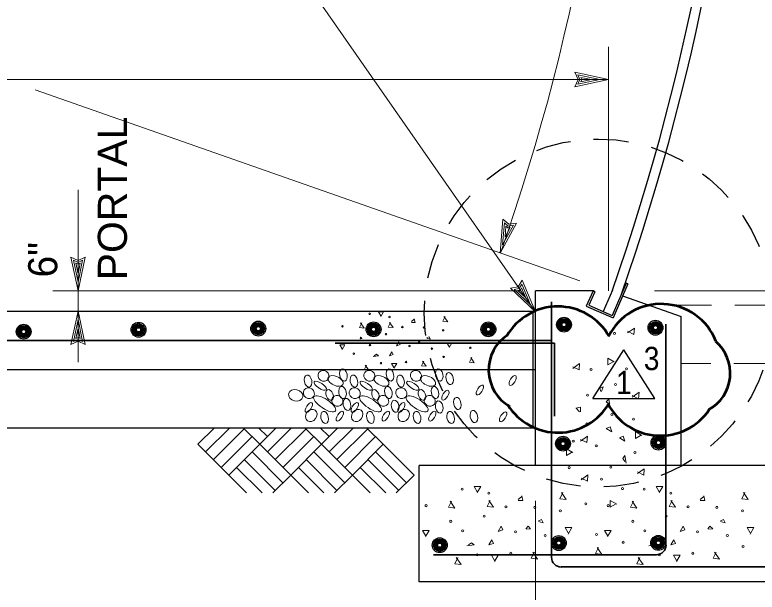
# Model space of a CAD drawing. Extents: x -24.3 to 17.7, y -17.6 to 12.4.
# Drawn here: x -5.978 to -2.791, y -12.561 to -10.082 of the extents above; entities that cross this region are included whole.
import ezdxf
from ezdxf.enums import TextEntityAlignment as Align

# ---------------------------------------------------------------- set-up
doc = ezdxf.new("R2010")
doc.units = 0
doc.header["$LTSCALE"] = 0.05
doc.linetypes.add('MEDIUM_DASHED', pattern=[4.5, 3, -1.5])
doc.layers.add('1', color=7, linetype='Continuous', lineweight=13)
doc.layers.add('2', color=7, linetype='Continuous', lineweight=13)

msp = doc.modelspace()

# ---------------------------------------------------------------- linework, layer by layer
at = {"layer": '1'}
for p, q in [((-3.42969, -11.2666), (-3.42969, -10.2186)), ((-3.42969, -10.3596), (-3.57369, -10.3286)), ((-3.46669, -10.3596), (-3.56069, -10.3396)), ((-3.55169, -10.3596), (-3.56069, -10.3396)), ((-3.50269, -10.3596), (-3.54769, -10.3506)), ((-3.54369, -10.3596), (-3.54769, -10.3506)), ((-3.46669, -10.3596), (-3.56069, -10.3796)), ((-3.56069, -10.3796), (-3.55169, -10.3596)), ((-3.50269, -10.3596), (-3.54769, -10.3696)), ((-3.54769, -10.3696), (-3.54369, -10.3596)), ((-3.55269, -11.2246), (-5.89069, -10.4036)), ((-3.89369, -11.1056), (-3.88269, -10.9586)), ((-3.89369, -11.1056), (-3.82369, -10.9766)), ((-3.88369, -11.0696), (-3.87569, -10.9746)), ((-3.88369, -11.0696), (-3.83769, -10.9856)), ((-3.87569, -10.9746), (-3.85969, -10.9886)), ((-3.87269, -11.0356), (-3.86969, -10.9896)), ((-3.86969, -10.9896), (-3.86169, -10.9966)), ((-3.85969, -10.9886), (-3.83769, -10.9856)), ((-3.87269, -11.0356), (-3.85169, -10.9946)), ((-3.86169, -10.9966), (-3.85169, -10.9946)), ((-5.70669, -11.2666), (-5.73769, -11.1226)), ((-5.70669, -11.2296), (-5.72669, -11.1356)), ((-5.72669, -11.1356), (-5.70669, -11.1446)), ((-5.70669, -11.1936), (-5.71669, -11.1486)), ((-5.71669, -11.1486), (-5.70669, -11.1526)), ((-5.70669, -11.2666), (-5.67569, -11.1226)), ((-5.70669, -11.2296), (-5.68669, -11.1356)), ((-5.70669, -11.1446), (-5.68669, -11.1356)), ((-5.70669, -11.1936), (-5.69769, -11.1486)), ((-5.70669, -11.1526), (-5.69769, -11.1486)), ((-3.81269, -11.2566), (-3.80069, -11.2376)), ((-3.76369, -11.3266), (-3.80069, -11.2376)), ((-3.74269, -11.3566), (-3.79969, -11.2206)), ((-3.80669, -11.2666), (-5.81469, -11.2666)), ((-3.83369, -11.2606), (-3.81269, -11.2566)), ((-3.76369, -11.3266), (-3.83369, -11.2606)), ((-3.81869, -11.2656), (-3.80769, -11.2626)), ((-3.78469, -11.2966), (-3.81869, -11.2656)), ((-3.80769, -11.2626), (-3.80269, -11.2546)), ((-3.78469, -11.2966), (-3.80269, -11.2546)), ((-3.23169, -11.2666), (-0.82769, -11.2666)), ((-5.70669, -11.3536), (-5.73769, -11.4976)), ((-5.70669, -11.3536), (-5.67569, -11.4976)), ((-5.70669, -11.5726), (-5.70669, -11.3536)), ((-5.70669, -11.3906), (-5.72669, -11.4846)), ((-5.70669, -11.3906), (-5.68669, -11.4846)), ((-5.70669, -11.4266), (-5.71569, -11.4716)), ((-5.70669, -11.4266), (-5.69669, -11.4716)), ((-5.70669, -11.4676), (-5.71569, -11.4716)), ((-5.69669, -11.4716), (-5.70669, -11.4676)), ((-5.70669, -11.4756), (-5.72669, -11.4846)), ((-5.68669, -11.4846), (-5.70669, -11.4756)), ((-5.19169, -11.9256), (-5.12069, -11.8546)), ((-5.15869, -11.9586), (-5.05469, -11.8546)), ((-5.12569, -11.9916), (-4.99269, -11.8596)), ((-4.92669, -11.9256), (-4.99769, -11.8546)), ((-4.89369, -11.8926), (-4.93169, -11.8546)), ((-4.92669, -11.9256), (-4.85569, -11.8546)), ((-4.92669, -11.9256), (-4.85569, -11.8546)), ((-4.89369, -11.9586), (-4.78969, -11.8546)), ((-4.86069, -11.8596), (-4.86569, -11.8546)), ((-4.86069, -11.9916), (-4.72769, -11.8596)), ((-4.66169, -11.9256), (-4.73269, -11.8546)), ((-4.62869, -11.8926), (-4.66669, -11.8546)), ((-4.66169, -11.9256), (-4.59069, -11.8546)), ((-4.62869, -11.9586), (-4.52369, -11.8546)), ((-4.59569, -11.8596), (-4.59969, -11.8546)), ((-4.59569, -11.9916), (-4.46269, -11.8596)), ((-4.39669, -11.9256), (-4.46769, -11.8546)), ((-5.09269, -12.0256), (-4.95969, -11.8926)), ((-4.82769, -12.0256), (-4.69469, -11.8926)), ((-4.56169, -12.0256), (-4.42969, -11.8926)), ((-5.05969, -12.0586), (-4.92669, -11.9256)), ((-4.79369, -12.0586), (-4.92669, -11.9256)), ((-4.79369, -12.0586), (-4.66169, -11.9256)), ((-4.52869, -12.0586), (-4.39669, -11.9256)), ((-4.26369, -12.0586), (-4.39669, -11.9256)), ((-4.82769, -12.0916), (-4.95969, -11.9586)), ((-4.56169, -12.0916), (-4.69469, -11.9586)), ((-4.29669, -12.0916), (-4.42969, -11.9586)), ((-4.86069, -12.1246), (-4.99269, -11.9916)), ((-4.59569, -12.1246), (-4.72769, -11.9916)), ((-4.32969, -12.1246), (-4.46269, -11.9916)), ((-4.91669, -12.1346), (-5.02669, -12.0256)), ((-4.65169, -12.1346), (-4.76069, -12.0256)), ((-4.38569, -12.1346), (-4.49569, -12.0256)), ((-4.87069, -12.1346), (-4.79369, -12.0586)), ((-4.71769, -12.1346), (-4.79369, -12.0586)), ((-4.60569, -12.1346), (-4.52869, -12.0586)), ((-4.34069, -12.1346), (-4.26369, -12.0586)), ((-3.74269, -14.5116), (-3.74269, -12.1686))]:
    msp.add_line(p, q, dxfattribs=at)
at = {"layer": '1', "lineweight": 25}
for p, q in [((-3.35369, -11.2336), (-3.41369, -11.3726)), ((-3.34569, -11.2366), (-3.40969, -11.3826)), ((-3.34569, -11.2366), (-3.35369, -11.2336)), ((-3.74269, -12.0166), (-3.74269, -11.2666)), ((-3.49469, -11.2666), (-3.74269, -11.2666)), ((-3.49569, -11.2666), (-3.52469, -11.3326)), ((-3.48869, -11.2706), (-3.49569, -11.2666)), ((-3.41269, -11.2646), (-3.45169, -11.3556)), ((-3.36869, -11.2886), (-3.11769, -11.3776)), ((-3.52469, -11.3326), (-3.40969, -11.3826)), ((-16.07569, -11.3546), (-3.74269, -11.3546)), ((-3.75269, -11.8546), (-3.75269, -11.3546)), ((-3.11769, -12.0166), (-3.11769, -11.3776)), ((-3.49654, -11.72945), (-3.36354, -11.52045)), ((-3.23054, -11.72945), (-3.36354, -11.52045)), ((-16.07569, -11.6046), (-3.74269, -11.6046)), ((-3.49654, -11.72945), (-3.23054, -11.72945)), ((-16.07569, -11.8546), (-3.74269, -11.8546)), ((-2.61769, -12.0166), (-4.24269, -12.0166))]:
    msp.add_line(p, q, dxfattribs=at)
at = {"layer": '1', "lineweight": 35}
for p, q in [((-3.67369, -12.4116), (-3.67369, -11.3136)), ((-3.18269, -12.3586), (-3.18269, -11.4106)), ((-9.84169, -11.4796), (-3.67137, -11.4796)), ((-3.6617, -11.49113), (-4.60307, -11.49113)), ((-3.6617, -11.80445), (-3.6617, -11.49113)), ((-4.18069, -12.4006), (-3.22369, -12.4006)), ((-3.63269, -12.4526), (-2.69869, -12.4526))]:
    msp.add_line(p, q, dxfattribs=at)
at = {"layer": '1', "linetype": 'MEDIUM_DASHED'}
for p, q in [((-2.23769, -11.3286), (-3.25769, -11.3286)), ((-2.24069, -11.5786), (-3.11769, -11.5786))]:
    msp.add_line(p, q, dxfattribs=at)
at = {"layer": '1'}
for points in [[(-4.84869, -9.9336), (-4.73269, -9.9336), (-3.74269, -11.3566), (-3.85069, -11.2556)], [(-3.57369, -10.3906), (-3.55969, -10.3596), (-3.57369, -10.3286)], [(-16.38769, -10.3596), (-9.90869, -10.3596), (-3.42969, -10.3596), (-3.57369, -10.3906)], [(-5.70669, -11.3536), (-5.70669, -11.2666), (-5.70669, -10.8326)], [(-3.88269, -10.9586), (-3.85669, -10.9806), (-3.82369, -10.9766)], [(-5.73769, -11.1226), (-5.70669, -11.1366), (-5.67569, -11.1226)], [(-3.85069, -11.2556), (-3.81669, -11.2496), (-3.79969, -11.2206)], [(-5.67569, -11.4976), (-5.70669, -11.4836), (-5.73769, -11.4976)], [(-4.45269, -12.1346), (-4.66169, -11.9256), (-4.59069, -11.8546)], [(-4.98269, -12.1346), (-5.05969, -12.0586), (-5.19169, -11.9256)]]:
    msp.add_lwpolyline(points, dxfattribs=at)
at = {"layer": '1', "lineweight": 25}
for points in [[(-3.48869, -11.2706), (-3.51369, -11.3286), (-3.41369, -11.3726)], [(-2.61769, -12.5166), (-4.24269, -12.5166), (-4.24269, -12.0166)]]:
    msp.add_lwpolyline(points, dxfattribs=at)
at = {"layer": '1', "linetype": 'MEDIUM_DASHED', "lineweight": 25}
msp.add_circle((-3.47269, -11.3626), 0.7473, dxfattribs=at)
at = {"layer": '1', "lineweight": 25}
for centre, radius in [((-5.44683, -11.43413), 0.0319), ((-5.44683, -11.43413), 0.02658), ((-4.93285, -11.42913), 0.0319), ((-4.93285, -11.42913), 0.02658), ((-4.93285, -11.42913), 0.02215), ((-4.43786, -11.43213), 0.0319), ((-4.43786, -11.43213), 0.02658), ((-3.94488, -11.43213), 0.0319), ((-3.94488, -11.43213), 0.02658), ((-3.62022, -11.41221), 0.0319), ((-3.62022, -11.41221), 0.02658), ((-3.62022, -11.41221), 0.02215), ((-3.62022, -11.41221), 0.01846), ((-3.62022, -11.41221), 0.01538), ((-3.62022, -11.41221), 0.01282), ((-3.62022, -11.41221), 0.01068), ((-3.62022, -11.41221), 0.0089), ((-3.22765, -11.42538), 0.0319), ((-3.22765, -11.42538), 0.02658), ((-3.22765, -11.42538), 0.02215), ((-3.22765, -11.42538), 0.01846), ((-5.93981, -11.44213), 0.0319), ((-5.93981, -11.44213), 0.02658), ((-5.93981, -11.44213), 0.02215), ((-5.93981, -11.44213), 0.01846), ((-5.93981, -11.44213), 0.01538), ((-5.93981, -11.44213), 0.01282), ((-5.93981, -11.44213), 0.01068), ((-5.93981, -11.44213), 0.0089), ((-5.44683, -11.43413), 0.02215), ((-5.44683, -11.43413), 0.01846), ((-5.44683, -11.43413), 0.01538), ((-5.44683, -11.43413), 0.01282), ((-5.44683, -11.43413), 0.01068), ((-5.44683, -11.43413), 0.0089), ((-4.93285, -11.42913), 0.01846), ((-4.93285, -11.42913), 0.01538), ((-4.93285, -11.42913), 0.01282), ((-4.93285, -11.42913), 0.01068), ((-4.93285, -11.42913), 0.0089), ((-4.43786, -11.43213), 0.02215), ((-4.43786, -11.43213), 0.01846), ((-4.43786, -11.43213), 0.01538), ((-4.43786, -11.43213), 0.01282), ((-4.43786, -11.43213), 0.01068), ((-4.43786, -11.43213), 0.0089), ((-3.94488, -11.43213), 0.02215), ((-3.94488, -11.43213), 0.01846), ((-3.94488, -11.43213), 0.01538), ((-3.94488, -11.43213), 0.01282), ((-3.94488, -11.43213), 0.01068), ((-3.94488, -11.43213), 0.0089), ((-3.22765, -11.42538), 0.01538), ((-3.22765, -11.42538), 0.01282), ((-3.22765, -11.42538), 0.01068), ((-3.22765, -11.42538), 0.0089), ((-3.62455, -11.92344), 0.0319), ((-3.62455, -11.92344), 0.02658), ((-3.62455, -11.92344), 0.02215), ((-3.62455, -11.92344), 0.01846), ((-3.62455, -11.92344), 0.01538), ((-3.62455, -11.92344), 0.01282), ((-3.62455, -11.92344), 0.01068), ((-3.62455, -11.92344), 0.0089), ((-3.2149, -11.91869), 0.0319), ((-3.2149, -11.91869), 0.02658), ((-3.2149, -11.91869), 0.02215), ((-3.2149, -11.91869), 0.01846), ((-3.2149, -11.91869), 0.01538), ((-3.2149, -11.91869), 0.01282), ((-3.2149, -11.91869), 0.01068), ((-3.2149, -11.91869), 0.0089), ((-4.15379, -12.35935), 0.0319), ((-3.6428, -12.3501), 0.0319), ((-3.6428, -12.3501), 0.02658), ((-3.6428, -12.3501), 0.02215), ((-3.6428, -12.3501), 0.01846), ((-3.21565, -12.34918), 0.0319), ((-3.21565, -12.34918), 0.02658), ((-3.21565, -12.34918), 0.02215), ((-3.21565, -12.34918), 0.01846), ((-4.15379, -12.35935), 0.02658), ((-4.15379, -12.35935), 0.02215), ((-4.15379, -12.35935), 0.01846), ((-4.15379, -12.35935), 0.01538), ((-4.15379, -12.35935), 0.01282), ((-4.15379, -12.35935), 0.01068), ((-4.15379, -12.35935), 0.0089), ((-3.6428, -12.3501), 0.01538), ((-3.6428, -12.3501), 0.01282), ((-3.6428, -12.3501), 0.01068), ((-3.6428, -12.3501), 0.0089), ((-3.21565, -12.34918), 0.01538), ((-3.21565, -12.34918), 0.01282), ((-3.21565, -12.34918), 0.01068), ((-3.21565, -12.34918), 0.0089)]:
    msp.add_circle(centre, radius, dxfattribs=at)
at = {"layer": '1'}
msp.add_arc((-12.59669, -8.0506), 9.224, 340.65884, 359.95031, dxfattribs=at)
at = {"layer": '1', "lineweight": 25}
for radius in [9.70818, 9.74984]:
    msp.add_arc((-12.57569, -8.05836), radius, 340.66927, 359.12919, dxfattribs=at)
at = {"layer": '1', "lineweight": 53}
for centre, radius, start, end in [((-3.64649, -11.58747), 0.25334, 29.90527, 149.99619), ((-3.20334, -11.57661), 0.25334, 21.83431, 152.92582), ((-3.76385, -11.60702), 0.18009, 122.74739, 240.5783), ((-3.08692, -11.62029), 0.18009, 299.4217, 48.99754), ((-3.64649, -11.62265), 0.25334, 211.92276, 330.09473), ((-3.20696, -11.63532), 0.25334, 207.07418, 326.09842)]:
    msp.add_arc(centre, radius, start, end, dxfattribs=at)
at = {"layer": '1', "lineweight": 35}
for centre, start, end in [((-3.22396, -12.35863), 270, 0), ((-3.63237, -12.41133), 180, 270)]:
    msp.add_arc(centre, 0.04167, start, end, dxfattribs=at)
at = {"layer": '1'}
for centre, major_axis, ratio in [((-4.71919, -11.6546), (-0.0055, 0.026), 0.599528), ((-4.65269, -11.6321), (-0.02021, 0.0142), 0.915279), ((-4.60119, -11.6536), (-0.0315, 0.015), 0.562188), ((-4.56719, -11.6286), (-0.0055, 0.026), 0.599528), ((-4.52219, -11.6546), (-0.0055, 0.026), 0.599528), ((-4.45569, -11.6321), (-0.02021, 0.0142), 0.915279), ((-4.40419, -11.6536), (-0.0315, 0.015), 0.562188), ((-4.36719, -11.6286), (-0.0055, 0.026), 0.599528), ((-4.32219, -11.6546), (-0.0055, 0.026), 0.599528), ((-4.25569, -11.6321), (-0.02021, 0.0142), 0.915279), ((-4.20419, -11.6536), (-0.0315, 0.015), 0.562188), ((-4.15619, -11.6286), (-0.0055, 0.026), 0.599528), ((-4.11119, -11.6436), (-0.0055, 0.026), 0.599528), ((-3.84069, -11.6521), (0.013, 0.0205), 0.445558), ((-4.66669, -11.6746), (-0.026, 0.017), 0.365968), ((-4.46969, -11.6746), (-0.026, 0.017), 0.365968), ((-4.26969, -11.6746), (-0.026, 0.017), 0.365968), ((-4.77219, -11.7156), (-0.03038, 0.00696), 0.790099), ((-4.71569, -11.7061), (-0.02021, 0.0142), 0.915279), ((-4.62669, -11.7141), (-0.009, 0.0225), 0.615421), ((-4.57119, -11.7036), (-0.0055, 0.026), 0.599528), ((-4.51869, -11.7061), (-0.02021, 0.0142), 0.915279), ((-4.42969, -11.7141), (-0.009, 0.0225), 0.615421), ((-4.37419, -11.7036), (-0.0055, 0.026), 0.599528), ((-4.31869, -11.7061), (-0.02021, 0.0142), 0.915279), ((-4.22969, -11.7141), (-0.009, 0.0225), 0.615421), ((-4.17419, -11.7036), (-0.0055, 0.026), 0.599528), ((-4.12969, -11.7151), (0.013, 0.0205), 0.445558), ((-3.98169, -11.6931), (0.013, 0.0205), 0.445558), ((-4.64769, -11.7521), (-0.04615, 0.03077), 0.357541), ((-4.59369, -11.7391), (-0.02021, 0.0142), 0.915279), ((-4.45069, -11.7521), (-0.04615, 0.03077), 0.357541), ((-4.39669, -11.7391), (-0.02021, 0.0142), 0.915279), ((-4.25069, -11.7521), (-0.04615, 0.03077), 0.357541), ((-4.19669, -11.7391), (-0.02021, 0.0142), 0.915279), ((-4.07819, -11.7506), (-0.0055, 0.026), 0.599528), ((-4.71569, -11.7681), (0.013, 0.0205), 0.445558), ((-4.55219, -11.7546), (-0.0055, 0.026), 0.599528), ((-4.51869, -11.7681), (0.013, 0.0205), 0.445558), ((-4.34519, -11.7626), (-0.0055, 0.026), 0.599528), ((-4.31869, -11.7681), (0.013, 0.0205), 0.445558), ((-4.15619, -11.7656), (-0.0055, 0.026), 0.599528), ((-4.70519, -11.8021), (0.0165, 0.0225), 0.822116), ((-4.64819, -11.8106), (-0.0055, 0.026), 0.599528), ((-4.58269, -11.8051), (0.013, 0.0205), 0.445558), ((-4.50819, -11.8021), (0.0165, 0.0225), 0.822116), ((-4.45119, -11.8106), (-0.0055, 0.026), 0.599528), ((-4.38569, -11.8051), (0.013, 0.0205), 0.445558), ((-4.30819, -11.8021), (0.0165, 0.0225), 0.822116), ((-4.25119, -11.8106), (-0.0055, 0.026), 0.599528), ((-4.18569, -11.8051), (0.013, 0.0205), 0.445558), ((-4.10719, -11.8106), (-0.0055, 0.026), 0.599528), ((-4.00719, -11.8066), (-0.0055, 0.026), 0.599528), ((-3.88169, -11.8081), (0.013, 0.0205), 0.445558)]:
    msp.add_ellipse(centre, major_axis=major_axis, ratio=ratio, dxfattribs=at)
at = {"layer": '2'}
for p, q in [((-4.27469, -11.3986), (-4.26369, -11.3886)), ((-3.55369, -11.7866), (-3.56769, -11.7706)), ((-3.81769, -12.1626), (-3.80169, -12.1496)), ((-3.03569, -12.1626), (-3.02069, -12.1496))]:
    msp.add_line(p, q, dxfattribs=at)
for points in [[(-4.40669, -11.3736), (-4.41669, -11.3566), (-4.39469, -11.3566), (-4.40669, -11.3776)], [(-4.48869, -11.4046), (-4.49869, -11.4246), (-4.47869, -11.4266), (-4.49369, -11.4046)], [(-4.36469, -11.4026), (-4.37469, -11.4226), (-4.35369, -11.4246), (-4.36969, -11.4026)], [(-4.26369, -11.3876), (-4.25969, -11.4026), (-4.27469, -11.4026)], [(-4.13069, -11.3776), (-4.14069, -11.3976), (-4.11969, -11.3996), (-4.13569, -11.3776)], [(-3.34769, -11.4406), (-3.32069, -11.4546), (-3.31769, -11.4266), (-3.34769, -11.4476)], [(-4.20969, -11.4676), (-4.19969, -11.4646), (-4.19469, -11.4746), (-4.20969, -11.4696)], [(-4.57269, -11.5156), (-4.58269, -11.4986), (-4.56069, -11.4986), (-4.57269, -11.5186)], [(-4.24969, -11.4936), (-4.24269, -11.4846), (-4.23469, -11.4936), (-4.24769, -11.4946)], [(-4.11369, -11.5066), (-4.12369, -11.4896), (-4.10169, -11.4896), (-4.11369, -11.5106)], [(-4.43469, -11.5456), (-4.42469, -11.5386), (-4.41669, -11.5456), (-4.43969, -11.5486)], [(-4.01569, -11.5536), (-4.02569, -11.5736), (-4.00569, -11.5756), (-4.02069, -11.5536)], [(-3.40969, -11.5716), (-3.43269, -11.5846), (-3.43269, -11.5556), (-3.40569, -11.5716)], [(-4.46869, -11.5856), (-4.47869, -11.6056), (-4.45869, -11.6076), (-4.47369, -11.5856)], [(-4.35069, -11.5956), (-4.36069, -11.5786), (-4.33869, -11.5786), (-4.35069, -11.5996)], [(-4.22269, -11.5686), (-4.23269, -11.5886), (-4.21269, -11.5906), (-4.22769, -11.5686)], [(-3.58269, -11.5936), (-3.55569, -11.6066), (-3.55369, -11.5796), (-3.58269, -11.6006)], [(-3.46169, -11.6986), (-3.46669, -11.6856), (-3.45269, -11.6786), (-3.45969, -11.6986)], [(-3.32769, -11.7166), (-3.30069, -11.7306), (-3.29769, -11.7026), (-3.32769, -11.7236)], [(-3.42769, -11.7526), (-3.43969, -11.7436), (-3.42769, -11.7326), (-3.42569, -11.7506)], [(-3.56969, -11.7706), (-3.54969, -11.7666), (-3.54969, -11.7866)], [(-3.29169, -11.8876), (-3.31369, -11.9006), (-3.31369, -11.8716), (-3.28669, -11.8876)], [(-3.54969, -11.9056), (-3.52269, -11.9186), (-3.51969, -11.8916), (-3.54969, -11.9126)], [(-3.58769, -11.9616), (-3.60969, -11.9746), (-3.60969, -11.9456), (-3.58269, -11.9616)], [(-3.35869, -11.9996), (-3.36769, -11.9866), (-3.35869, -11.9746), (-3.35369, -12.0066)], [(-3.30469, -12.0446), (-3.27769, -12.0586), (-3.27569, -12.0306), (-3.30469, -12.0516)], [(-3.54669, -12.0716), (-3.51969, -12.0846), (-3.51769, -12.0576), (-3.54669, -12.0786)], [(-3.99269, -12.1296), (-4.00569, -12.1066), (-3.97669, -12.1066), (-3.99269, -12.1336)], [(-3.21169, -12.1296), (-3.22469, -12.1066), (-3.19569, -12.1066), (-3.21169, -12.1336)], [(-3.62469, -12.1336), (-3.63769, -12.1606), (-3.61069, -12.1636), (-3.63169, -12.1336)], [(-2.84369, -12.1336), (-2.85669, -12.1606), (-2.82969, -12.1636), (-2.84969, -12.1336)], [(-4.10269, -12.1696), (-4.11569, -12.1966), (-4.08869, -12.1996), (-4.10969, -12.1696)], [(-3.93669, -12.1676), (-3.94969, -12.1936), (-3.92269, -12.1966), (-3.94369, -12.1676)], [(-3.80169, -12.1476), (-3.79769, -12.1676), (-3.81769, -12.1676)], [(-3.39869, -12.1836), (-3.42169, -12.1966), (-3.42169, -12.1676), (-3.39369, -12.1836)], [(-3.32169, -12.1696), (-3.33469, -12.1966), (-3.30769, -12.1996), (-3.32769, -12.1696)], [(-3.15569, -12.1676), (-3.16869, -12.1936), (-3.14169, -12.1966), (-3.16169, -12.1676)], [(-3.02069, -12.1476), (-3.01569, -12.1676), (-3.03569, -12.1676)], [(-3.72969, -12.2546), (-3.71669, -12.2496), (-3.70969, -12.2636), (-3.72969, -12.2576)], [(-2.94869, -12.2546), (-2.93569, -12.2496), (-2.92869, -12.2636), (-2.94869, -12.2576)], [(-4.21469, -12.3176), (-4.22769, -12.2956), (-4.19869, -12.2956), (-4.21469, -12.3226)], [(-3.78369, -12.2886), (-3.77469, -12.2776), (-3.76369, -12.2886), (-3.78169, -12.2906)], [(-3.60269, -12.3066), (-3.61569, -12.2836), (-3.58669, -12.2836), (-3.60269, -12.3116)], [(-3.43369, -12.3176), (-3.44669, -12.2956), (-3.41769, -12.2956), (-3.43369, -12.3226)], [(-3.00269, -12.2886), (-2.99369, -12.2776), (-2.98169, -12.2886), (-2.99969, -12.2906)], [(-2.82169, -12.3066), (-2.83469, -12.2836), (-2.80569, -12.2836), (-2.82169, -12.3116)], [(-4.03069, -12.3576), (-4.01769, -12.3496), (-4.00569, -12.3576), (-4.03769, -12.3626)], [(-3.24969, -12.3576), (-3.23569, -12.3496), (-3.22469, -12.3576), (-3.25569, -12.3626)], [(-3.74769, -12.3896), (-3.76169, -12.4156), (-3.73369, -12.4186), (-3.75469, -12.3896)], [(-3.47169, -12.3696), (-3.48569, -12.3956), (-3.45769, -12.3986), (-3.47869, -12.3696)], [(-2.96669, -12.3896), (-2.97969, -12.4156), (-2.95269, -12.4186), (-2.97369, -12.3896)], [(-4.07569, -12.4116), (-4.08969, -12.4386), (-4.06169, -12.4416), (-4.08269, -12.4116)], [(-3.91869, -12.4256), (-3.93169, -12.4026), (-3.90269, -12.4026), (-3.91869, -12.4296)], [(-3.29469, -12.4116), (-3.30769, -12.4386), (-3.28069, -12.4416), (-3.30169, -12.4116)], [(-3.13769, -12.4256), (-3.15069, -12.4026), (-3.12169, -12.4026), (-3.13769, -12.4296)]]:
    msp.add_lwpolyline(points, dxfattribs=at)
for points in [[(-4.33969, -11.5026), (-4.32969, -11.4856), (-4.32369, -11.4976)], [(-4.36969, -11.5456), (-4.35969, -11.5286), (-4.35369, -11.5406)], [(-3.41569, -11.8726), (-3.43869, -11.8586), (-3.42269, -11.8516)], [(-3.35869, -11.9126), (-3.38169, -11.8986), (-3.36569, -11.8916)], [(-3.90369, -12.3006), (-3.88969, -12.2776), (-3.88269, -12.2936)], [(-3.12169, -12.3006), (-3.10869, -12.2776), (-3.10169, -12.2936)], [(-3.94369, -12.3576), (-3.92969, -12.3356), (-3.92269, -12.3516)], [(-3.16169, -12.3576), (-3.14869, -12.3356), (-3.14169, -12.3516)]]:
    msp.add_lwpolyline(points, close=True, dxfattribs=at)
for centre, radius in [((-4.455, -11.36556), 0.00325), ((-4.36951, -11.37906), 0.00325), ((-4.5715, -11.41906), 0.00325), ((-4.31401, -11.42256), 0.00325), ((-4.22151, -11.42456), 0.00325), ((-4.13901, -11.43606), 0.00325), ((-4.492, -11.46956), 0.00325), ((-4.3845, -11.45306), 0.00325), ((-3.40371, -11.44964), 0.00433), ((-4.4535, -11.50006), 0.00325), ((-4.28351, -11.50356), 0.00325), ((-4.5225, -11.53706), 0.00325), ((-4.18751, -11.51506), 0.00325), ((-4.02251, -11.51156), 0.00325), ((-4.13701, -11.55055), 0.00325), ((-4.4065, -11.57755), 0.00325), ((-4.29851, -11.57255), 0.00325), ((-3.35171, -11.6023), 0.00433), ((-3.50437, -11.60497), 0.00433), ((-3.39904, -11.66964), 0.00433), ((-3.51971, -11.71497), 0.00433), ((-3.41437, -11.79763), 0.00433), ((-3.32238, -11.81763), 0.00433), ((-3.52237, -11.8383), 0.00433), ((-3.58037, -11.9123), 0.00433), ((-3.48171, -11.9323), 0.00433), ((-3.31571, -11.96163), 0.00433), ((-3.59837, -12.0263), 0.00433), ((-3.41904, -12.0243), 0.00433), ((-3.45971, -12.07563), 0.00433), ((-4.05741, -12.11813), 0.00433), ((-3.94341, -12.13613), 0.00433), ((-3.36971, -12.1163), 0.00433), ((-3.27588, -12.11813), 0.00433), ((-3.16188, -12.13613), 0.00433), ((-4.21274, -12.18946), 0.00433), ((-3.86941, -12.19413), 0.00433), ((-3.74608, -12.19679), 0.00433), ((-3.52704, -12.18163), 0.00433), ((-3.43121, -12.18946), 0.00433), ((-3.08788, -12.19413), 0.00433), ((-2.96455, -12.19679), 0.00433), ((-3.96341, -12.23479), 0.00433), ((-3.63608, -12.21213), 0.00433), ((-3.18188, -12.23479), 0.00433), ((-2.85455, -12.21213), 0.00433), ((-4.10674, -12.25679), 0.00433), ((-3.32521, -12.25679), 0.00433), ((-4.05541, -12.29746), 0.00433), ((-3.82874, -12.30213), 0.00433), ((-3.27388, -12.29746), 0.00433), ((-3.04721, -12.30213), 0.00433), ((-3.70075, -12.31746), 0.00433), ((-3.48075, -12.31279), 0.00433), ((-2.91922, -12.31746), 0.00433), ((-4.1474, -12.34679), 0.00433), ((-3.63341, -12.36479), 0.00433), ((-3.36588, -12.34679), 0.00433), ((-2.85188, -12.36479), 0.00433), ((-3.84874, -12.39412), 0.00433), ((-3.06721, -12.39412), 0.00433), ((-3.99274, -12.40079), 0.00433), ((-3.21121, -12.40079), 0.00433)]:
    msp.add_circle(centre, radius, dxfattribs=at)

# ---------------------------------------------------------------- texts
at = {"layer": '1', "width": 1.05}
msp.add_text('PORTAL', height=0.125, rotation=90, dxfattribs=at).set_placement((-5.49669, -11.2216))
at = {"layer": '1'}
msp.add_text('6"', height=0.125, rotation=90, dxfattribs=at).set_placement((-5.79569, -11.2096))
at = {"layer": '1', "width": 0.9}
for s, p in [('3', (-3.24421, -11.60745)), ('1', (-3.36321, -11.71045))]:
    msp.add_text(s, height=0.1, dxfattribs=at).set_placement(p, align=Align.CENTER)

doc.saveas('drawing.dxf')
